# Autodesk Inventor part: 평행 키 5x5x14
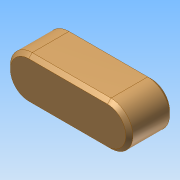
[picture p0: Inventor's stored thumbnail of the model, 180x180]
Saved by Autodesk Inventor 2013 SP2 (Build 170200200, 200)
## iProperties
Created: 2026-07
Part Number: 평행 키 5x5x14
Material: Generic
Document SubType Name: Modeling
Designer: a
Density: 1 g/cm^3
Author: a
변환 표준: STEP AP214IS
전처리기: Build: 200, Release: 2013 SP2 Update 6 - Date: Thu 07/17/2014
전송 단위: 밀리미터
불확실성: 0.01
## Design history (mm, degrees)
node "평행 키 5x5x141"
node "솔리드1"
node "기준1"
